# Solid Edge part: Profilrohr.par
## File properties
Username: ahadarics
Dokumentum tartalom típus: 0
Author: ahadarics
Last saved by: ahadarics
Revision: 78
Sűrűség: 0,000 kg/m^3
Pontosság: 0,990
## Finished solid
Body 1: solid body, 6 faces, 6 edges, 0 vertices.
  Faces by surface: cone 2, cylinder 2, plane 2
  Edges by curve: circle 6
Bounding box of the edges (mm): 26.500 x 26.500 x 83.000, from (-13.25, -13.25, -61.5) to (13.25, 13.25, 21.5).
Cylindrical faces by radius (mm): R12.5 x1, R13.25 x1
Conical faces (half-angle, radius in mm at the cone's reference point): 15 deg R12.567 x2
Planar faces by outward normal: +z 1, -z 1
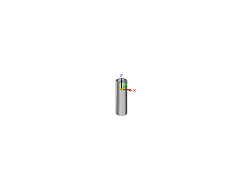
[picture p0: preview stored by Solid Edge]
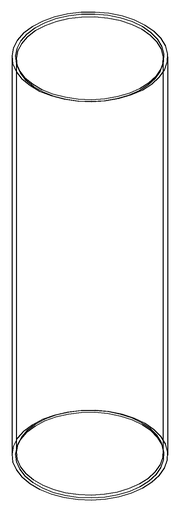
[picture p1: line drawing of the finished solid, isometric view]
